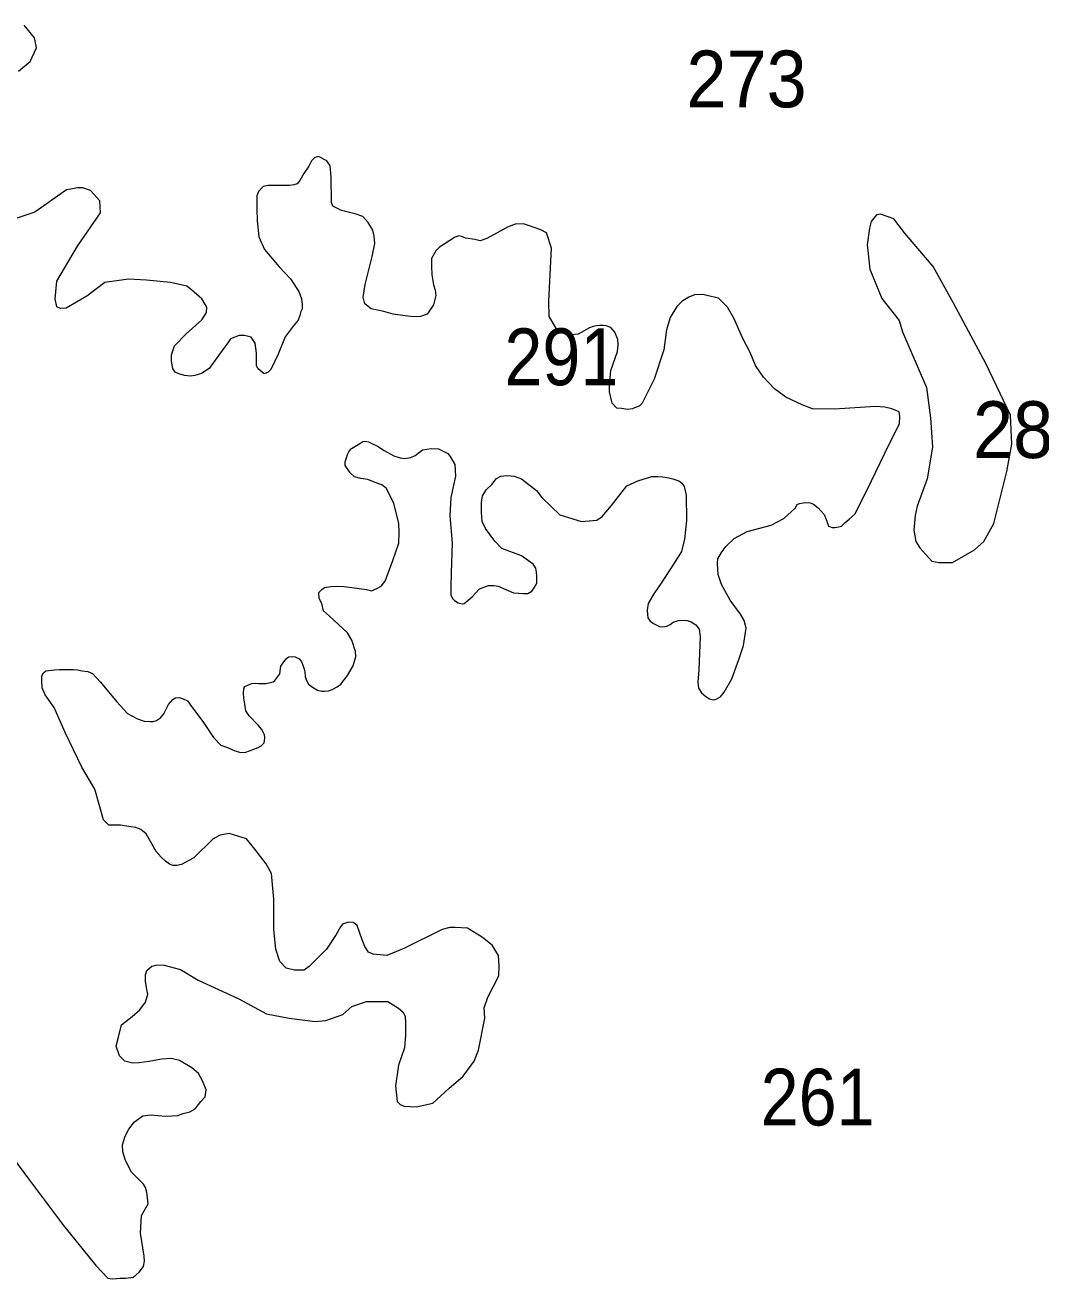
# Model space of a CAD drawing. Extents: x 445.4 to 500, y 8728.7 to 8784.
# Drawn here: x 485.347 to 488.212, y 8756.547 to 8760.081 of the extents above; entities that cross this region are included whole.
import ezdxf

# ---------------------------------------------------------------- set-up
doc = ezdxf.new("R2010")
doc.units = 0
doc.header["$LTSCALE"] = 0.064
doc.layers.add('2', color=7, linetype='Continuous', lineweight=13)
doc.layers.add('21', color=7, linetype='Continuous')

msp = doc.modelspace()

# ---------------------------------------------------------------- linework, layer by layer
at = {"layer": '2'}
for points in [[(485.3284, 8759.9512), (485.3612, 8759.9785), (485.3791, 8760.0172), (485.3733, 8760.0448), (485.3442, 8760.0812)], [(486.7694, 8759.5148), (486.7524, 8759.521), (486.7293, 8759.5195), (486.7077, 8759.5118), (486.6491, 8759.4794), (486.6306, 8759.4732), (486.6151, 8759.4763), (486.5905, 8759.4809), (486.5781, 8759.4856), (486.5689, 8759.4871), (486.5581, 8759.4825), (486.5161, 8759.4555), (486.5053, 8759.4448), (486.493, 8759.4232), (486.493, 8759.4232), (486.493, 8759.4016), (486.4945, 8759.377), (486.4992, 8759.3492), (486.5038, 8759.3338), (486.5053, 8759.3184), (486.4992, 8759.2922), (486.4807, 8759.266), (486.4621, 8759.2599), (486.4421, 8759.2583), (486.419, 8759.2614), (486.385, 8759.266), (486.3588, 8759.2737), (486.3233, 8759.2814), (486.3048, 8759.2953), (486.3002, 8759.3138), (486.3058, 8759.3502), (486.3258, 8759.4287), (486.3336, 8759.4657), (486.332, 8759.4857), (486.3274, 8759.5027), (486.315, 8759.5243), (486.2996, 8759.5412), (486.278, 8759.5489), (486.258, 8759.5535), (486.2395, 8759.5582), (486.2148, 8759.5705), (486.2148, 8759.5705), (486.2117, 8759.5813), (486.2101, 8759.6522), (486.2071, 8759.6845), (486.1978, 8759.6984), (486.1747, 8759.7107), (486.1747, 8759.7107), (486.1639, 8759.7076), (486.1546, 8759.6984), (486.1469, 8759.683), (486.133, 8759.6629), (486.1222, 8759.6429), (486.1145, 8759.6337), (486.1053, 8759.6306), (486.0929, 8759.629), (486.0775, 8759.629), (486.0513, 8759.629), (486.0328, 8759.629), (486.0189, 8759.626), (486.005, 8759.6121), (486.005, 8759.6121), (486.0004, 8759.5998), (486.0004, 8759.5813), (486.0004, 8759.5628), (486.0019, 8759.5289), (486.0065, 8759.4842), (486.022, 8759.4488), (486.0635, 8759.3999), (486.0959, 8759.366), (486.119, 8759.3306), (486.1267, 8759.309), (486.1283, 8759.2936), (486.1283, 8759.2813), (486.1252, 8759.2736), (486.1221, 8759.2628), (486.1175, 8759.2489), (486.1036, 8759.232), (486.0804, 8759.2027), (486.0604, 8759.1534), (486.0403, 8759.1102), (486.0403, 8759.1102), (486.0326, 8759.1025), (486.0218, 8759.0979), (486.0049, 8759.1118), (486.0049, 8759.1118), (486.0002, 8759.121), (486.0002, 8759.1565), (485.9956, 8759.1842), (485.9848, 8759.2011), (485.9663, 8759.2058), (485.9509, 8759.2058), (485.9262, 8759.1965), (485.9185, 8759.1857), (485.9077, 8759.1703), (485.866, 8759.1133), (485.8444, 8759.0994), (485.8259, 8759.0933), (485.8136, 8759.0917), (485.7966, 8759.0933), (485.7812, 8759.0979)], [(485.7812, 8759.0979), (485.7704, 8759.1025), (485.7642, 8759.1133), (485.7596, 8759.1333), (485.7596, 8759.1518), (485.7688, 8759.1765), (485.8012, 8759.2104), (485.846, 8759.2504), (485.8583, 8759.2705), (485.8599, 8759.2859), (485.846, 8759.309), (485.8167, 8759.3352), (485.8035, 8759.3451), (485.7572, 8759.3559), (485.6894, 8759.362), (485.6385, 8759.3651), (485.5721, 8759.3559), (485.5212, 8759.3173), (485.4626, 8759.2834), (485.4472, 8759.2819), (485.4364, 8759.2865), (485.4318, 8759.3096), (485.4364, 8759.3589), (485.495, 8759.4575), (485.5598, 8759.5515), (485.5582, 8759.5854), (485.532, 8759.6147), (485.5104, 8759.6224), (485.495, 8759.6224), (485.4811, 8759.6193), (485.4641, 8759.6163), (485.3742, 8759.5538), (485.3017, 8759.5292)], [(487.2884, 8758.1793), (487.2963, 8758.1812), (487.3081, 8758.1871), (487.3189, 8758.2009), (487.3406, 8758.2383), (487.3594, 8758.293), (487.3732, 8758.3324), (487.381, 8758.3815), (487.3751, 8758.4022), (487.3643, 8758.4209), (487.3357, 8758.4603), (487.3111, 8758.5045), (487.3013, 8758.5321), (487.2993, 8758.5635), (487.3003, 8758.5763), (487.3111, 8758.594), (487.3229, 8758.6108), (487.3466, 8758.6334), (487.3836, 8758.6536), (487.4506, 8758.6713), (487.487, 8758.69), (487.5186, 8758.7195), (487.5245, 8758.7293), (487.5314, 8758.7323), (487.5412, 8758.7342), (487.5491, 8758.7352), (487.5609, 8758.7342), (487.5708, 8758.7303), (487.5836, 8758.7205), (487.6003, 8758.7018), (487.6082, 8758.6831), (487.6131, 8758.6683), (487.623, 8758.6644), (487.6308, 8758.6644), (487.6417, 8758.6664), (487.6496, 8758.6683), (487.6584, 8758.6782), (487.6712, 8758.688), (487.688, 8758.7037), (487.7343, 8758.7968), (487.7836, 8758.9001), (487.8131, 8758.9572), (487.8141, 8758.9778), (487.8121, 8758.9906), (487.7915, 8758.9995), (487.7718, 8759.0044), (487.7452, 8759.0063), (487.6299, 8758.9985), (487.5676, 8758.9998), (487.5381, 8759.0106), (487.4928, 8759.0322), (487.4603, 8759.0559), (487.4298, 8759.0883), (487.4071, 8759.1218), (487.3921, 8759.1578), (487.3714, 8759.1981), (487.3458, 8759.2552), (487.3281, 8759.2857), (487.3025, 8759.3112), (487.27, 8759.3191), (487.2582, 8759.322), (487.2345, 8759.3211), (487.2188, 8759.3142), (487.1991, 8759.3024), (487.1853, 8759.2876), (487.1666, 8759.2571), (487.1557, 8759.2217), (487.1488, 8759.1656), (487.121, 8759.0833), (487.0876, 8759.0154), (487.0787, 8759.0066), (487.0659, 8759.0026), (487.06, 8758.9997), (487.0462, 8758.9977), (487.0294, 8759.0007), (487.0157, 8759.0017), (487.0029, 8759.0154), (486.995, 8759.0469), (486.9947, 8759.0662), (486.9987, 8759.1075), (487.0174, 8759.1606), (487.0194, 8759.1803), (487.0184, 8759.1951), (487.0105, 8759.2157), (486.9987, 8759.2285), (486.9859, 8759.2334), (486.977, 8759.2344), (486.9672, 8759.2344), (486.9583, 8759.2334), (486.9494, 8759.2315), (486.9386, 8759.2275), (486.9071, 8759.2098), (486.8874, 8759.2079), (486.8716, 8759.2093), (486.8454, 8759.2247), (486.8253, 8759.2601), (486.8238, 8759.3032), (486.8315, 8759.4527), (486.8176, 8759.4958), (486.8018, 8759.5041), (486.7694, 8759.5148)], [(486.0046, 8758.0444), (486.0125, 8758.0493), (486.0214, 8758.0582), (486.0224, 8758.0641), (486.0234, 8758.0719), (486.0224, 8758.0808), (486.0145, 8758.0956), (486.0046, 8758.1074), (485.979, 8758.1339), (485.9692, 8758.1477), (485.9672, 8758.1664), (485.9643, 8758.1841), (485.9633, 8758.1988), (485.9643, 8758.2097), (485.9662, 8758.2166), (485.9751, 8758.2205), (485.982, 8758.2234), (485.9869, 8758.2254), (485.9968, 8758.2264), (486.0056, 8758.2254), (486.0174, 8758.2254), (486.0273, 8758.2254), (486.047, 8758.2293), (486.047, 8758.2293), (486.0519, 8758.2333), (486.0657, 8758.252), (486.0687, 8758.2736), (486.0765, 8758.2864), (486.0854, 8758.2962), (486.0913, 8758.3002), (486.1012, 8758.3012), (486.109, 8758.3002), (486.1199, 8758.2943), (486.1268, 8758.2874), (486.1317, 8758.2736), (486.1346, 8758.2657), (486.1356, 8758.2579), (486.1366, 8758.2451), (486.1406, 8758.2333), (486.1465, 8758.2234), (486.1573, 8758.2146), (486.1721, 8758.2067), (486.1839, 8758.2038), (486.1918, 8758.2038), (486.2036, 8758.2048), (486.2154, 8758.2087), (486.2272, 8758.2156), (486.2371, 8758.2234), (486.2568, 8758.248), (486.2727, 8758.2752), (486.2796, 8758.3008), (486.2786, 8758.3155), (486.2688, 8758.347), (486.256, 8758.3677), (486.2057, 8758.4149), (486.189, 8758.4296), (486.1841, 8758.4503), (486.1762, 8758.4651), (486.1752, 8758.4818), (486.1841, 8758.4897), (486.1919, 8758.4956), (486.2097, 8758.4985), (486.2294, 8758.4995), (486.2461, 8758.4985), (486.2688, 8758.4956), (486.2894, 8758.4926), (486.3101, 8758.4897), (486.3239, 8758.4867), (486.3387, 8758.4926), (486.3515, 8758.4995), (486.3627, 8758.5139), (486.3843, 8758.5719), (486.4011, 8758.6211), (486.4021, 8758.6506), (486.4011, 8758.6762), (486.3873, 8758.7333), (486.3656, 8758.7753), (486.3528, 8758.7851), (486.3341, 8758.792), (486.3134, 8758.7999), (486.2937, 8758.8029), (486.276, 8758.8078), (486.2642, 8758.8186), (486.2494, 8758.8393), (486.2494, 8758.8501), (486.2534, 8758.8609), (486.2563, 8758.8707), (486.2612, 8758.8796), (486.2681, 8758.8875), (486.2908, 8758.9012), (486.2996, 8758.9071), (486.3056, 8758.9081), (486.3154, 8758.9062), (486.3253, 8758.9012), (486.341, 8758.8943), (486.3597, 8758.8816), (486.3873, 8758.8668), (486.405, 8758.8609), (486.4168, 8758.8589), (486.4346, 8758.8619), (486.4474, 8758.8678)], [(486.4474, 8758.8678), (486.4681, 8758.8835), (486.4927, 8758.8875), (486.5134, 8758.8865), (486.5321, 8758.8776), (486.539, 8758.8737), (486.5459, 8758.8648), (486.5587, 8758.8422), (486.5606, 8758.81), (486.5478, 8758.749), (486.5449, 8758.6978), (486.5518, 8758.6211), (486.5488, 8758.5379), (486.5478, 8758.4946), (486.5478, 8758.4749), (486.5528, 8758.4651), (486.5577, 8758.4592), (486.5685, 8758.4523), (486.5685, 8758.4523), (486.5794, 8758.4493), (486.5853, 8758.4503), (486.6075, 8758.4691), (486.6282, 8758.4917), (486.6538, 8758.5016), (486.6695, 8758.5016), (486.6814, 8758.4996), (486.7247, 8758.4809), (486.7523, 8758.4789), (486.7651, 8758.4789), (486.7759, 8758.4858), (486.7828, 8758.4947), (486.7907, 8758.5075), (486.7907, 8758.5261), (486.7897, 8758.5389), (486.7877, 8758.5498), (486.7799, 8758.5616), (486.7468, 8758.585), (486.6917, 8758.6056), (486.672, 8758.6263), (486.6454, 8758.6617), (486.6365, 8758.6814), (486.6345, 8758.7079), (486.6345, 8758.7355), (486.6375, 8758.7542), (486.6483, 8758.7719), (486.6631, 8758.7857), (486.6769, 8758.8034), (486.6887, 8758.8093), (486.7055, 8758.8112), (486.7261, 8758.8093), (486.7468, 8758.8024), (486.7889, 8758.7689), (486.8047, 8758.7492), (486.8549, 8758.7001), (486.916, 8758.6814), (486.9485, 8758.6843), (486.9593, 8758.6853), (486.9741, 8758.6961), (487.0007, 8758.7266), (487.044, 8758.7827), (487.0755, 8758.7965), (487.1149, 8758.8083), (487.1317, 8758.8083), (487.1455, 8758.8073), (487.1622, 8758.8053), (487.174, 8758.8024), (487.1908, 8758.7965), (487.1996, 8758.7896), (487.2055, 8758.7807), (487.2114, 8758.7561), (487.2124, 8758.6843), (487.2065, 8758.6322), (487.1986, 8758.597), (487.1759, 8758.5616), (487.1424, 8758.5104), (487.1198, 8758.478), (487.104, 8758.4504), (487.1011, 8758.4317), (487.1021, 8758.4199), (487.103, 8758.4101), (487.1099, 8758.4012), (487.1188, 8758.3943), (487.1357, 8758.3859), (487.1456, 8758.3849), (487.1564, 8758.3868), (487.1663, 8758.3918), (487.1751, 8758.3977), (487.1899, 8758.4026), (487.2007, 8758.4036), (487.2145, 8758.4026), (487.2254, 8758.3987), (487.2382, 8758.3908), (487.248, 8758.378), (487.251, 8758.3573), (487.247, 8758.2639), (487.2441, 8758.2285), (487.2461, 8758.2117), (487.2549, 8758.1989), (487.2667, 8758.1881), (487.2776, 8758.1822), (487.2884, 8758.1793)], [(486.6434, 8757.2812), (486.6421, 8757.3111), (486.652, 8757.3407), (486.6832, 8757.4005), (486.6845, 8757.4292), (486.682, 8757.4578), (486.6645, 8757.4877), (486.6371, 8757.5089), (486.5946, 8757.5351), (486.5597, 8757.5376), (486.5447, 8757.5376), (486.5235, 8757.5314), (486.415, 8757.4778), (486.3675, 8757.4578), (486.3288, 8757.4616), (486.3151, 8757.4678), (486.3051, 8757.484), (486.2977, 8757.5027), (486.2839, 8757.5426), (486.2727, 8757.5513), (486.259, 8757.5526), (486.2427, 8757.5463), (486.2365, 8757.5388), (486.224, 8757.5177), (486.1974, 8757.4757), (486.1487, 8757.427), (486.1341, 8757.4173), (486.1073, 8757.4173), (486.083, 8757.4222), (486.066, 8757.4416), (486.0538, 8757.4757), (486.0489, 8757.5316), (486.0489, 8757.6166), (486.0416, 8757.6895), (486.027, 8757.7163), (485.9954, 8757.7576), (485.9711, 8757.7868), (485.9227, 8757.8024), (485.8971, 8757.7974), (485.8774, 8757.7876), (485.8226, 8757.7333), (485.7881, 8757.7146), (485.7753, 8757.7116), (485.7635, 8757.7116), (485.7546, 8757.7156), (485.7428, 8757.7244), (485.731, 8757.7353), (485.7172, 8757.751), (485.6886, 8757.8012), (485.6738, 8757.813), (485.6591, 8757.8189), (485.6453, 8757.8208), (485.6167, 8757.8258), (485.6, 8757.8258), (485.5832, 8757.8258), (485.5684, 8757.8403), (485.5437, 8757.9269), (485.5073, 8757.9889), (485.4603, 8758.0868), (485.4288, 8758.1576), (485.4041, 8758.1931), (485.3953, 8758.2127), (485.3943, 8758.2324), (485.3943, 8758.2462), (485.3992, 8758.255), (485.4061, 8758.2609), (485.4288, 8758.2639), (485.4445, 8758.2649), (485.4721, 8758.2649), (485.4829, 8758.2649), (485.4947, 8758.2639), (485.5085, 8758.2609), (485.5243, 8758.259), (485.5371, 8758.2531), (485.5597, 8758.2285), (485.606, 8758.1734), (485.6356, 8758.1409), (485.6641, 8758.1252), (485.6829, 8758.1193), (485.6996, 8758.1183), (485.7085, 8758.1183), (485.7173, 8758.1212), (485.7291, 8758.1281), (485.738, 8758.1399), (485.7518, 8758.1655), (485.7636, 8758.1803), (485.7705, 8758.1842), (485.7813, 8758.1852), (485.7932, 8758.1822), (485.805, 8758.1763), (485.8168, 8758.1606), (485.848, 8758.1182), (485.8786, 8758.0729), (485.8993, 8758.0513), (485.918, 8758.0444), (485.9387, 8758.0355), (485.9554, 8758.0306), (485.9692, 8758.0316), (485.98, 8758.0355), (485.9918, 8758.0395), (486.0046, 8758.0444)], [(485.258, 8756.961), (485.3566, 8756.8289), (485.4555, 8756.6974), (485.5466, 8756.5839), (485.5803, 8756.549), (485.594, 8756.5465), (485.6052, 8756.5478), (485.614, 8756.549), (485.6302, 8756.549), (485.6526, 8756.5515), (485.6689, 8756.5652), (485.6813, 8756.5814), (485.6839, 8756.597), (485.6826, 8756.6107), (485.6727, 8756.6755), (485.6752, 8756.7254), (485.6939, 8756.7578), (485.6926, 8756.7753), (485.6901, 8756.7915), (485.6864, 8756.8039), (485.6814, 8756.8139), (485.6477, 8756.8475), (485.6302, 8756.88), (485.6227, 8756.9049), (485.6215, 8756.9248), (485.6295, 8756.9491), (485.6395, 8756.969), (485.6557, 8756.9889), (485.6794, 8757.0064), (485.7006, 8757.0089), (485.7443, 8757.0051), (485.7618, 8757.0064), (485.778, 8757.0076), (485.793, 8757.0126), (485.8117, 8757.0176), (485.8266, 8757.0263), (485.8429, 8757.0463), (485.8553, 8757.06), (485.8578, 8757.0799), (485.8479, 8757.1049), (485.8365, 8757.1257), (485.8178, 8757.1419), (485.7829, 8757.1619), (485.7592, 8757.1681), (485.7317, 8757.1656), (485.6968, 8757.1594), (485.6693, 8757.1556), (485.6506, 8757.1544), (485.6282, 8757.1606), (485.6132, 8757.1756), (485.6044, 8757.203), (485.6107, 8757.2279), (485.6194, 8757.2628), (485.6494, 8757.2865), (485.6706, 8757.3052), (485.6868, 8757.3264), (485.693, 8757.3488), (485.6905, 8757.3625), (485.6868, 8757.3862), (485.6868, 8757.4037), (485.6905, 8757.4161), (485.7043, 8757.4286), (485.7192, 8757.4323), (485.7392, 8757.4311), (485.7854, 8757.4186), (485.8353, 8757.3887), (485.9501, 8757.3364), (486.0282, 8757.2936), (486.0918, 8757.2812), (486.1655, 8757.2724), (486.1954, 8757.2749), (486.2428, 8757.2924), (486.269, 8757.3148), (486.3102, 8757.3285), (486.3701, 8757.3285), (486.4001, 8757.3098), (486.4125, 8757.2999), (486.4188, 8757.2874), (486.42, 8757.2674), (486.42, 8757.2338), (486.4175, 8757.1976), (486.4001, 8757.149), (486.3913, 8757.0904), (486.3963, 8757.0468), (486.4051, 8757.0381), (486.4163, 8757.0331), (486.45, 8757.0319), (486.4974, 8757.0418), (486.5423, 8757.083), (486.5822, 8757.1179), (486.6134, 8757.1602), (486.6259, 8757.1914), (486.6434, 8757.2812)]]:
    msp.add_lwpolyline(points, dxfattribs=at)
msp.add_lwpolyline([(488.1298, 8758.8993), (488.1263, 8758.9815), (488.0577, 8759.1254), (487.9651, 8759.2968), (487.9078, 8759.4002), (487.8272, 8759.4957), (487.7972, 8759.535), (487.7597, 8759.5481), (487.7485, 8759.5462), (487.7335, 8759.5275), (487.7279, 8759.5088), (487.7222, 8759.462), (487.7297, 8759.3927), (487.7635, 8759.3103), (487.8122, 8759.2485), (487.8216, 8759.2167), (487.8891, 8759.0594), (487.9004, 8758.9741), (487.906, 8758.8917), (487.891, 8758.8018), (487.8629, 8758.725), (487.8573, 8758.6988), (487.8535, 8758.6576), (487.8592, 8758.6258), (487.8704, 8758.6071), (487.9042, 8758.5696), (487.9248, 8758.5659), (487.9623, 8758.5659), (488.0242, 8758.6015), (488.0504, 8758.6258), (488.0785, 8758.6764), (488.116, 8758.8224)], close=True, dxfattribs=at)

# ---------------------------------------------------------------- texts
at = {"layer": '21'}
for s, width, p in [('273', 0.95, (487.2121, 8759.8493)), ('291', 0.9, (486.6988, 8759.066)), ('282', 0.95, (488.0202, 8758.8606)), ('261', 0.9, (487.4214, 8756.9791))]:
    msp.add_text(s, height=0.16, dxfattribs=dict(at, width=width)).set_placement(p)

doc.saveas('drawing.dxf')
